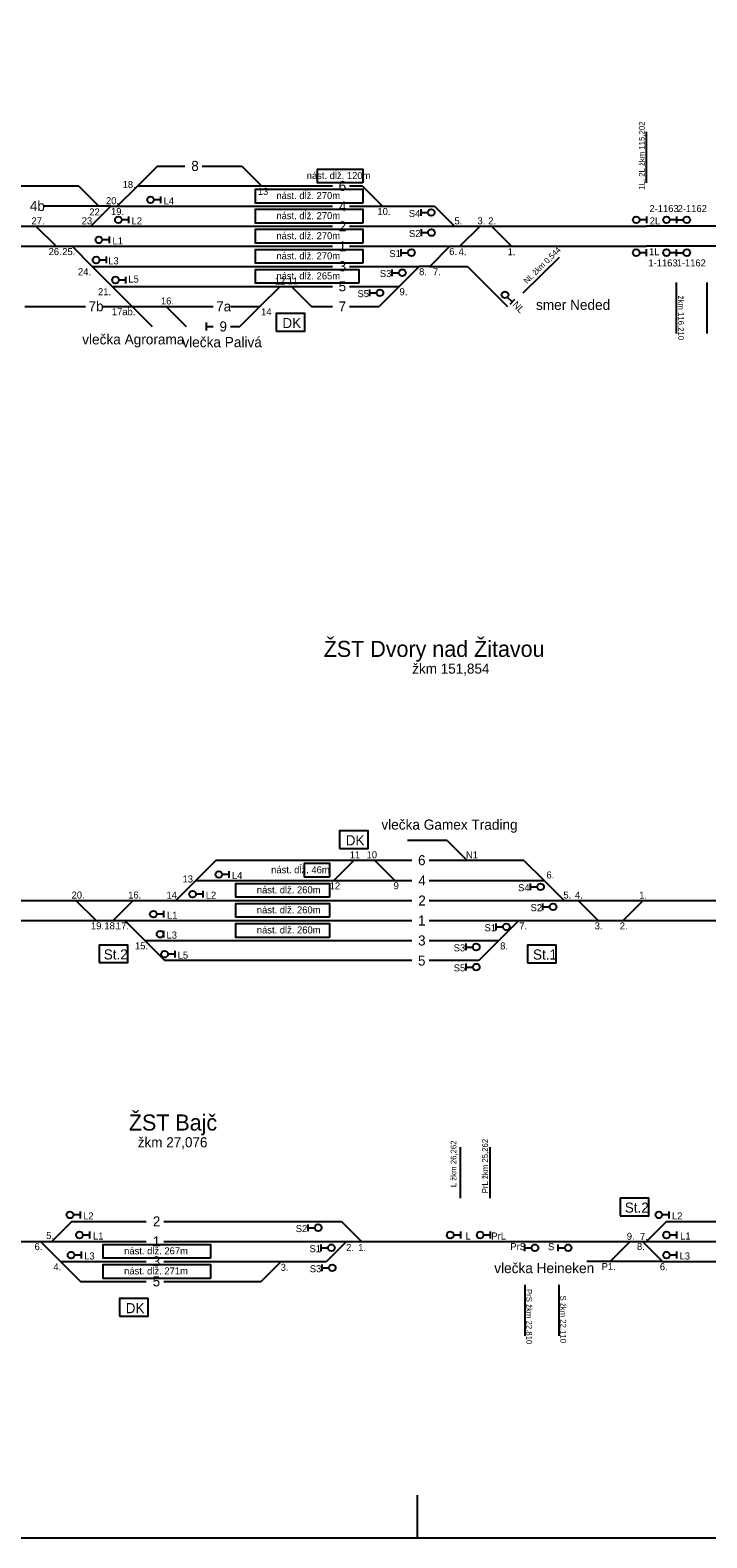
# Model space of a CAD drawing. Extents: x -119 to 851, y -238 to 59.
# Drawn here: x 52.5 to 119.9, y -238 to -87.8 of the extents above; entities that cross this region are included whole.
import ezdxf

# ---------------------------------------------------------------- set-up
doc = ezdxf.new("R2010")
doc.units = 0
for name, color, linetype in [('budova', 7, 'Continuous'), ('Level 2', 7, 'Continuous'), ('nastupistia', 7, 'Continuous'), ('netlač', 7, 'Continuous'), ('popisky navestidla', 7, 'Continuous'), ('popisky stanic a zastavok', 7, 'Continuous'), ('PU_navestidla', 7, 'Continuous'), ('PU_oznacenie navestidiel', 7, 'Continuous'), ('PU_stan_kolaje', 7, 'Continuous'), ('PU_vlecky', 7, 'Continuous')]:
    doc.layers.add(name, color=color, linetype=linetype)

msp = doc.modelspace()

# ---------------------------------------------------------------- linework, layer by layer
at = {"layer": 'budova'}
for points in [[(76.96, -117.75), (79.83, -117.75), (79.83, -116.01), (76.96, -116.01)], [(83.27, -169.3), (86.13, -169.3), (86.13, -167.55), (83.27, -167.55)], [(59.32, -180.69), (62.18, -180.69), (62.18, -178.94), (59.32, -178.94)], [(102.02, -180.7), (104.88, -180.7), (104.88, -178.95), (102.02, -178.95)], [(111.24, -205.92), (114.11, -205.92), (114.11, -204.17), (111.24, -204.17)], [(111.24, -205.92), (114.11, -205.92), (114.11, -204.17), (111.24, -204.17)], [(61.35, -215.92), (64.22, -215.92), (64.22, -214.17), (61.35, -214.17)]]:
    msp.add_lwpolyline(points, close=True, dxfattribs=at)
at = {"layer": 'Level 2'}
for p, q in [((53.81, -103.31), (47.81, -103.31)), ((57.3, -103.31), (53.81, -103.31)), ((82.57, -103.31), (63.14, -103.31)), ((85.57, -103.31), (84.29, -103.31)), ((60.5, -105.31), (53.81, -105.31)), ((60.5, -105.31), (82.57, -105.31)), ((84.29, -105.31), (92.75, -105.31)), ((51.39, -107.3), (67.59, -107.3)), ((67.59, -107.3), (82.57, -107.3)), ((84.29, -107.3), (91.19, -107.3)), ((91.19, -107.3), (113.86, -107.3)), ((39.78, -109.3), (66.39, -109.3)), ((66.39, -109.3), (82.57, -109.3)), ((84.29, -109.3), (92.19, -109.3)), ((92.19, -109.3), (110.49, -109.3)), ((110.49, -109.3), (113.86, -109.3)), ((58.63, -111.3), (82.57, -111.3)), ((84.29, -111.3), (91.22, -111.3)), ((92.27, -111.3), (96.03, -111.3)), ((84.29, -113.3), (89.22, -113.3)), ((59.69, -115.3), (62.62, -115.3)), ((72.42, -115.3), (75.35, -115.3)), ((84.29, -115.3), (87.22, -115.3)), ((70.01, -117.7), (70.01, -116.9)), ((72.42, -117.3), (73.35, -117.3)), ((94.01, -168.5), (90.05, -168.5)), ((92.45, -168.5), (92.3, -168.5)), ((90.48, -170.5), (70.96, -170.5)), ((90.1, -170.5), (89.88, -170.5)), ((101.66, -170.5), (92.2, -170.5)), ((68.96, -172.49), (90.48, -172.49)), ((92.2, -172.49), (103.66, -172.49)), ((49.49, -174.49), (59.31, -174.49)), ((59.31, -174.49), (75.5, -174.49)), ((75.5, -174.49), (90.48, -174.49)), ((92.2, -174.49), (99.1, -174.49)), ((99.1, -174.49), (121.77, -174.49)), ((49.49, -176.49), (74.3, -176.49)), ((74.3, -176.49), (90.48, -176.49)), ((92.2, -176.49), (100.1, -176.49)), ((100.1, -176.49), (118.4, -176.49)), ((118.4, -176.49), (121.77, -176.49)), ((63.89, -178.49), (90.48, -178.49)), ((92.2, -178.49), (99.16, -178.49)), ((90.48, -180.49), (65.89, -180.49)), ((73.07, -180.49), (72.78, -180.49)), ((97.16, -180.49), (92.2, -180.49)), ((93.34, -180.49), (92.88, -180.49)), ((56.6, -206.47), (64.03, -206.47)), ((65.76, -206.47), (83.48, -206.47)), ((115.86, -206.47), (134.94, -206.47)), ((49.06, -208.47), (64.03, -208.47)), ((65.76, -208.47), (72.66, -208.47)), ((72.66, -208.47), (95.33, -208.47)), ((105.07, -208.47), (112.78, -208.47)), ((109.79, -208.47), (113.85, -208.47)), ((112.78, -208.47), (134.94, -208.47)), ((55.47, -210.47), (64.03, -210.47)), ((65.76, -210.47), (81.98, -210.47)), ((115.47, -210.47), (134.94, -210.47)), ((57.47, -212.46), (64.03, -212.46)), ((65.76, -212.46), (75.48, -212.46))]:
    msp.add_line(p, q, dxfattribs=at)
at = {"layer": 'nastupistia'}
for points in [[(85.6, -102.99), (81.09, -102.99), (81.09, -101.61), (85.6, -101.61)], [(85.6, -104.99), (74.9, -104.99), (74.9, -103.61), (85.6, -103.61)], [(85.6, -106.99), (74.9, -106.99), (74.9, -105.61), (85.6, -105.61)], [(85.6, -108.99), (74.9, -108.99), (74.9, -107.61), (85.6, -107.61)], [(85.6, -110.99), (74.9, -110.99), (74.9, -109.61), (85.6, -109.61)], [(85.21, -112.99), (74.9, -112.99), (74.9, -111.61), (85.21, -111.61)], [(82.28, -172.17), (79.8, -172.17), (79.8, -170.79), (82.28, -170.79)], [(82.28, -174.17), (72.95, -174.17), (72.95, -172.79), (82.28, -172.79)], [(82.28, -176.17), (72.95, -176.17), (72.95, -174.79), (82.28, -174.79)], [(82.28, -178.17), (72.95, -178.17), (72.95, -176.78), (82.28, -176.78)], [(70.43, -210.15), (59.73, -210.15), (59.73, -208.77), (70.43, -208.77)], [(70.43, -212.15), (59.73, -212.15), (59.73, -210.77), (70.43, -210.77)]]:
    msp.add_lwpolyline(points, close=True, dxfattribs=at)
at = {"layer": 'netlač'}
for p, q in [((65.13, -101.31), (67.88, -101.31)), ((69.61, -101.31), (73.55, -101.31)), ((127.6, -107.3), (113.86, -107.3)), ((127.6, -109.3), (113.86, -109.3)), ((92.27, -111.3), (91.22, -111.3)), ((60.63, -113.3), (82.57, -113.3)), ((51.92, -115.29), (57.97, -115.29)), ((62.62, -115.3), (70.69, -115.3)), ((80.49, -115.3), (82.57, -115.3)), ((70.01, -117.3), (70.69, -117.3)), ((95.33, -208.47), (105.07, -208.47))]:
    msp.add_line(p, q, dxfattribs=at)
at = {"layer": 'popisky navestidla'}
for p, q in [((113.86, -102.99), (113.86, -97.9)), ((101.57, -113.93), (105.21, -110.38)), ((116.83, -112.91), (116.83, -118)), ((119.87, -112.91), (119.87, -118)), ((95.33, -204.15), (95.33, -199.06)), ((98.3, -204.15), (98.3, -199.06)), ((101.74, -212.78), (101.74, -217.87)), ((105.12, -212.78), (105.12, -217.87)), ((91.05, -238.01), (91.05, -233.77))]:
    msp.add_line(p, q, dxfattribs=at)
msp.add_lwpolyline([(-118.95, -238.01), (851.05, -238.01), (851.05, 58.99), (-118.95, 58.99)], close=True, dxfattribs=at)
at = {"layer": 'PU_navestidla'}
for p, q in [((65.45, -104.67), (64.78, -104.67)), ((65.45, -104.34), (65.45, -105.01)), ((62.26, -106.67), (61.59, -106.67)), ((62.26, -106.33), (62.26, -107)), ((91.41, -106.28), (91.41, -105.61)), ((91.41, -105.94), (92.08, -105.94)), ((113.86, -106.67), (113.19, -106.67)), ((113.86, -106.33), (113.86, -107)), ((116.87, -106.67), (116.2, -106.67)), ((116.87, -106.34), (116.87, -107.01)), ((116.87, -106.34), (116.87, -107.01)), ((116.87, -106.67), (117.54, -106.67)), ((91.44, -108.28), (91.44, -107.6)), ((91.44, -107.94), (92.11, -107.94)), ((60.31, -108.67), (59.64, -108.67)), ((60.31, -108.33), (60.31, -109)), ((89.43, -110.28), (89.43, -109.6)), ((113.86, -110.28), (113.86, -109.6)), ((116.87, -110.28), (116.87, -109.61)), ((116.87, -110.28), (116.87, -109.61)), ((60.03, -110.67), (59.36, -110.67)), ((60.03, -110.33), (60.03, -111)), ((89.43, -109.94), (90.1, -109.94)), ((113.86, -109.94), (113.19, -109.94)), ((116.87, -109.94), (116.2, -109.94)), ((116.87, -109.94), (117.54, -109.94)), ((61.97, -112.67), (61.29, -112.67)), ((61.97, -112.33), (61.97, -113)), ((88.54, -112.27), (88.54, -111.6)), ((88.54, -111.94), (89.21, -111.94)), ((86.3, -114.27), (86.3, -113.6)), ((86.3, -113.94), (86.98, -113.94)), ((100.48, -114.85), (100, -114.38)), ((100.72, -114.62), (100.24, -115.09)), ((72.26, -171.9), (71.59, -171.9)), ((72.26, -171.57), (72.26, -172.24)), ((69.65, -173.86), (68.98, -173.86)), ((69.65, -173.52), (69.65, -174.19)), ((102.31, -173.47), (102.31, -172.79)), ((102.31, -173.13), (102.98, -173.13)), ((65.74, -175.52), (65.74, -176.19)), ((103.55, -175.47), (103.55, -174.79)), ((103.55, -175.13), (104.22, -175.13)), ((65.74, -175.86), (65.07, -175.86)), ((98.9, -177.46), (98.9, -176.79)), ((98.9, -177.13), (99.58, -177.13)), ((65.74, -177.52), (65.74, -178.19)), ((66.86, -179.86), (66.18, -179.86)), ((66.86, -179.52), (66.86, -180.19)), ((95.9, -179.46), (95.9, -178.79)), ((95.9, -179.13), (96.57, -179.13)), ((95.9, -181.46), (95.9, -180.79)), ((95.9, -181.13), (96.57, -181.13)), ((57.43, -205.83), (56.76, -205.83)), ((57.43, -205.5), (57.43, -206.17)), ((116.11, -205.83), (115.44, -205.83)), ((116.11, -205.5), (116.11, -206.17)), ((80.15, -207.44), (80.15, -206.77)), ((80.15, -207.1), (80.82, -207.1)), ((58.36, -207.83), (57.69, -207.83)), ((58.36, -207.49), (58.36, -208.17)), ((81.46, -209.44), (81.46, -208.77)), ((95.33, -207.83), (94.65, -207.83)), ((95.33, -207.49), (95.33, -208.17)), ((98.3, -207.83), (97.63, -207.83)), ((98.3, -207.49), (98.3, -208.17)), ((101.74, -209.44), (101.74, -208.77)), ((105.07, -209.44), (105.07, -208.77)), ((116.87, -207.83), (116.19, -207.83)), ((116.87, -207.49), (116.87, -208.17)), ((57.54, -209.83), (56.87, -209.83)), ((57.54, -209.49), (57.54, -210.17)), ((81.46, -209.1), (82.13, -209.1)), ((101.74, -209.1), (102.41, -209.1)), ((105.07, -209.1), (105.74, -209.1)), ((116.87, -209.83), (116.19, -209.83)), ((116.87, -209.49), (116.87, -210.17)), ((81.55, -211.44), (81.55, -210.77)), ((81.55, -211.1), (82.22, -211.1))]:
    msp.add_line(p, q, dxfattribs=at)
for centre in [(64.44, -104.67), (61.25, -106.67), (92.42, -105.94), (112.85, -106.67), (115.86, -106.67), (117.88, -106.67), (92.44, -107.94), (59.3, -108.67), (90.44, -109.94), (112.85, -109.94), (115.86, -109.94), (117.88, -109.94), (59.02, -110.67), (60.96, -112.66), (89.54, -111.94), (87.31, -113.94), (99.77, -114.14), (71.25, -171.9), (68.64, -173.86), (103.32, -173.13), (64.73, -175.86), (104.56, -175.13), (99.91, -177.13), (65.4, -177.86), (65.85, -179.85), (96.91, -179.13), (96.91, -181.13), (56.42, -205.83), (115.1, -205.83), (81.16, -207.1), (57.36, -207.83), (82.47, -209.1), (94.32, -207.83), (97.29, -207.83), (102.75, -209.1), (106.07, -209.1), (115.86, -207.83), (56.53, -209.83), (115.86, -209.83), (82.56, -211.1)]:
    msp.add_circle(centre, 0.336, dxfattribs=at)
at = {"layer": 'PU_stan_kolaje'}
msp.add_line((115.47, -210.47), (107.92, -210.47), dxfattribs=at)
for points in [[(65.13, -101.31), (63.14, -103.31)], [(73.55, -101.31), (75.55, -103.31)], [(57.3, -103.31), (59.3, -105.31)], [(63.14, -103.31), (61.14, -105.31)], [(85.57, -103.31), (87.57, -105.31)], [(60.5, -105.31), (58.5, -107.3)], [(92.75, -105.31), (94.75, -107.3)], [(53.03, -107.3), (55.03, -109.3)], [(97.28, -107.3), (95.28, -109.3)], [(98.43, -107.3), (100.43, -109.3)], [(56.63, -109.3), (58.63, -111.3)], [(94.27, -109.3), (92.27, -111.3)], [(58.63, -111.3), (60.62, -113.3)], [(91.22, -111.3), (89.22, -113.3)], [(96.03, -111.3), (98.03, -113.3)], [(60.63, -113.3), (62.62, -115.3)], [(77.35, -113.3), (75.35, -115.3)], [(78.49, -113.3), (80.49, -115.3)], [(89.22, -113.3), (87.22, -115.3)], [(98.03, -113.3), (100.03, -115.3)], [(62.62, -115.3), (64.62, -117.3)], [(66.01, -115.3), (68.01, -117.3)], [(75.35, -115.3), (73.35, -117.3)], [(94.01, -168.5), (96.01, -170.5)], [(70.96, -170.5), (68.96, -172.49)], [(84.7, -170.5), (82.71, -172.49)], [(86.79, -170.5), (88.79, -172.49)], [(101.66, -170.5), (103.66, -172.49)], [(68.96, -172.49), (66.97, -174.49)], [(103.66, -172.49), (105.66, -174.49)], [(57.02, -174.49), (59.02, -176.49)], [(62.73, -174.49), (60.73, -176.49)], [(107.06, -174.49), (109.06, -176.49)], [(113.54, -174.49), (111.54, -176.49)], [(61.89, -176.49), (63.89, -178.49)], [(101.16, -176.49), (99.16, -178.49)], [(63.89, -178.49), (65.89, -180.49)], [(99.16, -178.49), (97.16, -180.49)], [(56.6, -206.47), (54.6, -208.47)], [(83.48, -206.47), (85.48, -208.47)], [(115.86, -206.47), (113.86, -208.47)], [(53.48, -208.47), (55.47, -210.47)], [(83.98, -208.47), (81.98, -210.47)], [(112.25, -208.47), (110.25, -210.47)], [(113.47, -208.47), (115.47, -210.47)], [(55.47, -210.47), (57.47, -212.46)], [(77.48, -210.47), (75.48, -212.46)]]:
    msp.add_lwpolyline(points, dxfattribs=at)

# ---------------------------------------------------------------- texts
at = {"layer": 'budova'}
for s, p in [('DK', (77.59, -117.45)), ('DK', (83.9, -169)), ('St.2', (59.79, -180.37)), ('St.1', (102.56, -180.38)), ('St.2', (111.71, -205.6)), ('DK', (61.98, -215.62))]:
    msp.add_text(s, height=1.004, dxfattribs=at).set_placement(p)
at = {"layer": 'nastupistia'}
for s, p in [('nást. dĺž. 120m', (80.01, -102.6)), ('nást. dĺž. 270m', (76.99, -104.6)), ('nást. dĺž. 270m', (76.99, -106.6)), ('nást. dĺž. 270m', (76.99, -108.6)), ('nást. dĺž. 270m', (76.99, -110.6)), ('nást. dĺž. 265m', (76.99, -112.6)), ('nást. dĺž. 46m', (76.47, -171.78)), ('nást. dĺž. 260m', (75.04, -173.78)), ('nást. dĺž. 260m', (75.04, -175.78)), ('nást. dĺž. 260m', (75.04, -177.78)), ('nást. dĺž. 267m', (61.82, -209.76)), ('nást. dĺž. 271m', (61.82, -211.76))]:
    msp.add_text(s, height=0.7, dxfattribs=at).set_placement(p)
at = {"layer": 'popisky navestidla'}
for s, rotation, p in [('1L, 2L žkm 115,202', 90, (113.69, -103.67)), ('NL žkm 0,544', 44.3476, (101.97, -113.07)), ('žkm 116,210', 270, (117.02, -114.22)), ('PrL žkm 25,262', 90, (98.07, -203.67)), ('L žkm 26,262', 90, (94.93, -203.06)), ('PrS žkm 22,810', 270, (101.89, -213.21)), ('S žkm 22,110', 270, (105.28, -213.86))]:
    msp.add_text(s, height=0.5793, rotation=rotation, dxfattribs=at).set_placement(p)
at = {"layer": 'popisky stanic a zastavok'}
for s, height, p in [('ŽST Dvory nad Žitavou', 1.6, (81.71, -150.22)), ('žkm 151,854', 1.0044, (90.53, -151.89)), ('ŽST Bajč', 1.6, (62.29, -197.42)), ('žkm 27,076', 1.004, (63.18, -199.09))]:
    msp.add_text(s, height=height, dxfattribs=at).set_placement(p)
at = {"layer": 'PU_oznacenie navestidiel'}
for s, p in [('18.', (61.67, -103.49)), ('13', (75.14, -104.18)), ('20.', (60.01, -105.11)), ('L4', (65.75, -105.12)), ('27.', (52.59, -107.12)), ('23.', (57.59, -107.11)), ('22.', (58.35, -106.23)), ('19.', (60.51, -106.19)), ('L2', (62.56, -107.12)), ('10.', (87.06, -106.18)), ('S4', (90.18, -106.38)), ('5.', (94.73, -107.12)), ('3.', (97.03, -107.11)), ('2.', (98.1, -107.12)), ('2-1163', (114.16, -105.89)), ('2L', (114.19, -107.12)), ('2-1162', (116.97, -105.89)), ('S2', (90.2, -108.38)), ('26.', (54.29, -110.18)), ('25.', (55.65, -110.18)), ('L1', (60.66, -109.12)), ('S1', (88.25, -110.38)), ('6.', (94.21, -110.18)), ('4.', (95.15, -110.19)), ('1.', (100.04, -110.19)), ('1L', (114.12, -110.19)), ('L3', (60.23, -111.1)), ('1-1163', (114.06, -111.31)), ('1-1162', (116.87, -111.31)), ('24.', (57.22, -112.19)), ('L5', (62.24, -112.92)), ('12', (76.83, -113.12)), ('11', (78.12, -113.11)), ('S3', (87.3, -112.37)), ('8.', (91.21, -112.18)), ('7.', (92.59, -112.19)), ('21.', (59.22, -114.18)), ('S5', (85.07, -114.37)), ('9.', (89.26, -114.18)), ('17ab.', (60.6, -116.17)), ('16.', (65.48, -115.1)), ('14', (75.46, -116.19)), ('11', (84.3, -170.3)), ('10', (85.98, -170.29)), ('N1', (95.88, -170.31)), ('13.', (67.64, -172.7)), ('L4', (72.56, -172.35)), ('12', (82.3, -173.38)), ('9', (88.67, -173.37)), ('6.', (103.9, -172.3)), ('20.', (56.58, -174.3)), ('16.', (62.22, -174.3)), ('14.', (66.04, -174.31)), ('L2', (69.95, -174.31)), ('S4', (101.08, -173.57)), ('5.', (105.59, -174.3)), ('4.', (106.74, -174.31)), ('1.', (113.14, -174.31)), ('L1', (66.09, -176.31)), ('S2', (102.32, -175.56)), ('19.', (58.51, -177.37)), ('18.', (59.85, -177.37)), ('17.', (61, -177.38)), ('S1', (97.73, -177.56)), ('7.', (101.19, -177.38)), ('3.', (108.71, -177.37)), ('2.', (111.21, -177.38)), ('15.', (62.9, -179.36)), ('L3', (66.04, -178.29)), ('8.', (99.29, -179.37)), ('L5', (67.15, -180.29)), ('S3', (94.66, -179.56)), ('S5', (94.66, -181.56)), ('L2', (57.73, -206.28)), ('L2', (116.41, -206.28)), ('S2', (78.92, -207.54)), ('6.', (52.89, -209.34)), ('5.', (54.05, -208.23)), ('L1', (58.72, -208.28)), ('S1', (80.29, -209.54)), ('2.', (83.94, -209.42)), ('1.', (85.14, -209.42)), ('L', (95.84, -208.28)), ('PrL', (98.41, -208.28)), ('PrS', (100.3, -209.34)), ('S', (104.06, -209.34)), ('9.', (111.91, -208.31)), ('8.', (112.92, -209.32)), ('7.', (113.22, -208.32)), ('L1', (117.22, -208.28)), ('L3', (57.84, -210.27)), ('L3', (117.17, -210.27)), ('4.', (54.77, -211.35)), ('3.', (77.42, -211.4)), ('S3', (80.32, -211.54)), ('P1.', (109.4, -211.33)), ('6.', (115.2, -211.34))]:
    msp.add_text(s, height=0.7, dxfattribs=at).set_placement(p)
msp.add_text('NL', height=0.7, rotation=315, dxfattribs=at).set_placement((100.46, -115.19))
at = {"layer": 'PU_stan_kolaje'}
for s, height, p in [('8', 1, (68.51, -101.79)), ('6', 1, (83.2, -103.79)), ('4b', 1.004, (52.42, -105.79)), ('4', 1, (83.23, -105.81)), ('2', 1, (83.21, -107.81)), ('1', 1, (83.2, -109.81)), ('3', 1, (83.2, -111.79)), ('5', 1, (83.19, -113.79)), ('7b', 1.004, (58.27, -115.78)), ('7a', 1.004, (70.99, -115.79)), ('7', 1, (83.19, -115.8)), ('9', 1, (71.32, -117.79)), ('6', 1, (91.11, -170.98)), ('4', 1, (91.14, -173)), ('2', 1, (91.13, -175)), ('1', 1, (91.11, -176.99)), ('3', 1, (91.11, -178.98)), ('5', 1, (91.1, -180.98)), ('2', 1, (64.68, -206.97)), ('1', 1, (64.67, -208.97)), ('3', 1, (64.66, -210.95)), ('5', 1, (64.66, -212.95))]:
    msp.add_text(s, height=height, dxfattribs=at).set_placement(p)
at = {"layer": 'PU_vlecky'}
for s, p in [('smer Neded', (102.86, -115.64)), ('vlečka Agrorama', (57.64, -119.08)), ('vlečka Palivá', (67.62, -119.36)), ('vlečka Gamex Trading', (87.45, -167.44)), ('vlečka Heineken', (98.7, -211.63))]:
    msp.add_text(s, height=1.015, dxfattribs=at).set_placement(p)

doc.saveas('drawing.dxf')
